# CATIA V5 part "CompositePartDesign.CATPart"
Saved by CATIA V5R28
Part number: Composite MBD
Bounding box of the stored display mesh (mm): x -54 to 96, y -104.114 to 14.853, z -24.35 to 72.398
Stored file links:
  C:\Users\jvl2147\Documents\2CES-COEXISTENCE\CompositePartDesign.CATPart
  C:\Users\jvl2147\Documents\ASME Y14.37\PartExamples\ASME-Y14.37_COMPOSITES-A.CATMaterial
  C:\Program Files\Dassault Systemes\B28SP3PRALL\win_b64\startup\composites\LaminateColors.txt
  C:\Program Files\Dassault Systemes\B28SP3PRALL\win_b64\startup\composites\DropOffPattern1BackSlash.txt
  C:\Program Files\Dassault Systemes\B28SP3PRALL\win_b64\startup\composites\DropOffPattern1Backslash.txt
  C:\Program Files\Dassault Systemes\B28SP3PRALL\win_b64\startup\composites\DropOffPattern1InverseV.txt
  C:\Program Files\Dassault Systemes\B28SP3PRALL\win_b64\startup\composites\DropOffPattern1InverseW.txt
  C:\Program Files\Dassault Systemes\B28SP3PRALL\win_b64\startup\composites\DropOffPattern1Slash.txt
  C:\Program Files\Dassault Systemes\B28SP3PRALL\win_b64\startup\composites\DropOffPattern1V.txt
  C:\Program Files\Dassault Systemes\B28SP3PRALL\win_b64\startup\composites\DropOffPattern1V_Symetry.txt
  C:\Program Files\Dassault Systemes\B28SP3PRALL\win_b64\startup\composites\DropOffPattern1V_Symetry_2Consecutive.txt
  C:\Program Files\Dassault Systemes\B28SP3PRALL\win_b64\startup\composites\DropOffPattern1W.txt
  C:\Program Files\Dassault Systemes\B28SP3PRALL\win_b64\startup\composites\DropOffPattern2Cross.txt
  C:\Program Files\Dassault Systemes\B28SP3PRALL\win_b64\startup\composites\DropOffPattern2Diamond.txt
  C:\Program Files\Dassault Systemes\B28SP3PRALL\win_b64\startup\composites\DropOffPattern2Socks.txt
  C:\Program Files\Dassault Systemes\B28SP3PRALL\win_b64\startup\composites\DropOffPattern45AfterOthers.txt
  C:\Program Files\Dassault Systemes\B28SP3PRALL\win_b64\startup\composites\DropOffPattern4TwinDiamonds45.txt
  C:\Program Files\Dassault Systemes\B28SP3PRALL\win_b64\startup\composites\DropOffPattern5Cross_Pseudo_Sym.txt
  C:\Program Files\Dassault Systemes\B28SP3PRALL\win_b64\startup\composites\DropOffPattern5Diamond_Pseudo_Sym.txt
  C:\Program Files\Dassault Systemes\B28SP3PRALL\win_b64\startup\composites\DropOffPattern5Socks_Pseudo_Sym.txt
  C:\Users\jvl2147\Desktop\LaserExportTest.ply
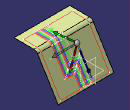
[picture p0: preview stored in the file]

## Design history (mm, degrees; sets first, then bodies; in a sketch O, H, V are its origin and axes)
Parameters
  `MBD Version - 787N4-1115 Rev` = "A"
AxisSystem1: origin (0, -29.9559, 49.1095), X (1, 0, 0), Y (0, 0.5207, -0.8537), Z (0, 0.8537, 0.5207)
CompParametersFeature1 "CATCoParametersFeatName": Value 0, Value 45, Value -45, Value 90
CompStacking1 "Stacking"
Set1 "CONSTRUCTION DATA"
  Sketch1 on yz-plane, origin (0, 0, 0), H (0, 1, 0), V (0, 0, 1)
    line L1 (-104.1144, 72.3983) -> (-50.835, 72.3983)
    line L2 (-40.6865, 66.7012) -> (14.853, -24.35)
    arc A1 centre (-50.835, 60.5109) radius 11.8875 from (-50.835, 72.3983) to (-40.6865, 66.7012) cw
    radius A1 = 11.8875
    horizontal: L1 H
    coincidence: L2 O
    tangency: A1 L1, A1 L2
  Extrude1: Element1 Sketch1, Lim1 96, Lim2 54
  Plane1: type Offset, RefPlane yz-plane, Offset 87
  Plane2: type Offset, RefPlane yz-plane, Offset 44, reversed
  Plane3: type Offset, RefPlane zx-plane, Offset -87
  Plane4: type Offset, RefPlane xy-plane, Offset -20
  MultiSel1
  Point1: type OnCurve, Support Sketch1, Ratio 0.5
  Line1: type Normal, RefPoint Point1, RefSkin Extrude1, Start 0, End 20
  Plane5: type Offset, RefPlane ZX plane of AxisSystem1, Offset 20
  Set2 "PlyBoundaryCurves for - Boeing MBD"
    DatumCurve1 to DatumCurve32
Set3 "ENGINEERING DATA"
  Set4 "COMPOSITES DEFINITION DATA"
    AxisSystem2 "Rosette": origin (0, -29.9559, 49.1095), X (1, 0, 0), Y (0, 0.5207, -0.8537), Z (0, 0.8537, 0.5207)
    DatumSurface1 "Definition Surface": linked copy from another document
Body1 (main body)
